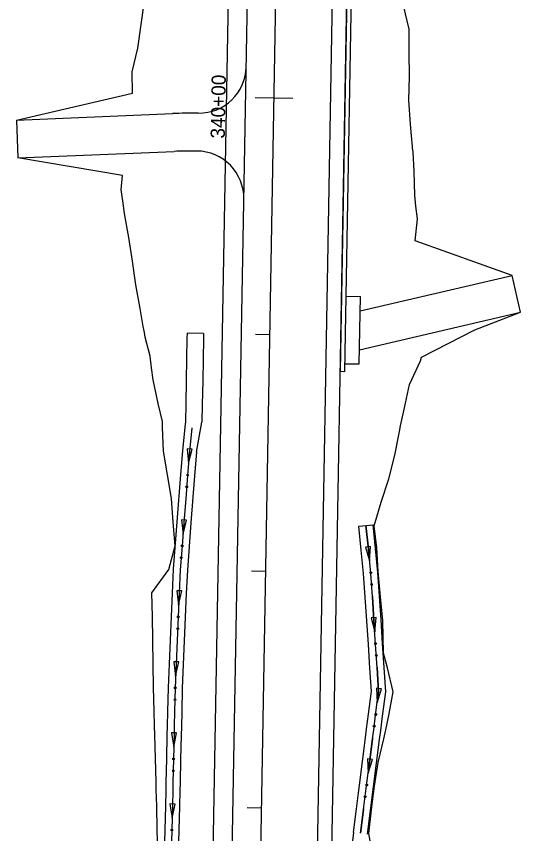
# Model space of a CAD drawing. Extents: x 948761 to 996004, y 1858548 to 1925175.
# Drawn here: x 960871.7 to 961084.7, y 1904759.1 to 1905104.5 of the extents above; entities that cross this region are included whole.
import ezdxf

# ---------------------------------------------------------------- set-up
doc = ezdxf.new("R2010")
doc.units = 0
for name, color, linetype in [('62', 7, 'Continuous'), ('R_Horz Alg', 7, 'Continuous'), ('R_Horz Alg Annot', 7, 'Continuous'), ('R_Proposed Const Limits', 7, 'Continuous'), ('R_Proposed Road', 7, 'Continuous')]:
    doc.layers.add(name, color=color, linetype=linetype)

msp = doc.modelspace()

# ---------------------------------------------------------------- linework, layer by layer
at = {"layer": '62'}
for p, q in [((960950.79, 1904970.5), (960943.79, 1904970.63)), ((960947.84, 1904920.32), (960950.12, 1904932.95)), ((960945.99, 1904921.55), (960943.88, 1904921.72)), ((960943.88, 1904921.72), (960944.44, 1904915.65)), ((960944.44, 1904915.65), (960945.99, 1904921.55)), ((960943.62, 1904891.61), (960941.51, 1904891.77)), ((960941.51, 1904891.77), (960942.1, 1904885.71)), ((960942.1, 1904885.71), (960943.62, 1904891.61)), ((961016.39, 1904888.98), (961022.36, 1904889.58)), ((961021.33, 1904880.43), (961019.22, 1904880.22)), ((961019.22, 1904880.22), (961020.87, 1904874.35)), ((961020.87, 1904874.35), (961021.33, 1904880.43)), ((960941.56, 1904861.68), (960939.45, 1904861.77)), ((960939.45, 1904861.77), (960940.26, 1904855.73)), ((960940.26, 1904855.73), (960941.56, 1904861.68)), ((961023.73, 1904850.45), (961021.62, 1904850.32)), ((961021.62, 1904850.32), (961023.06, 1904844.4)), ((961023.06, 1904844.4), (961023.73, 1904850.45)), ((960940.3, 1904831.67), (960938.19, 1904831.75)), ((960938.19, 1904831.75), (960939, 1904825.72)), ((960939, 1904825.72), (960940.3, 1904831.67)), ((961025.9, 1904820.27), (961023.8, 1904820.54)), ((961023.8, 1904820.54), (961024.09, 1904814.45)), ((961024.09, 1904814.45), (961025.9, 1904820.27)), ((960939.41, 1904801.66), (960937.3, 1904801.71)), ((960937.3, 1904801.71), (960938.22, 1904795.69)), ((960938.22, 1904795.69), (960939.41, 1904801.66)), ((961022.1, 1904790.47), (961020, 1904790.74)), ((961020, 1904790.74), (961020.29, 1904784.65)), ((961020.29, 1904784.65), (961022.1, 1904790.47)), ((960938.72, 1904771.63), (960936.6, 1904771.68)), ((960936.6, 1904771.68), (960937.51, 1904765.66)), ((960937.51, 1904765.66), (960938.72, 1904771.63))]:
    msp.add_line(p, q, dxfattribs=at)
for points in [[(960943.79, 1904970.63), (960943.75, 1904968.63), (960943.43, 1904950.63), (960943.26, 1904940.63), (960943.13, 1904933.2), (960942.89, 1904930.89), (960941.86, 1904920.88), (960941.04, 1904910.85), (960939.49, 1904890.87), (960937.94, 1904870.85), (960937.47, 1904860.8), (960936.21, 1904830.81), (960935.8, 1904820.79), (960935.57, 1904810.76), (960935.42, 1904804.59), (960935.33, 1904800.77), (960935.1, 1904790.77), (960934.86, 1904780.77), (960934.79, 1904777.53), (960934.64, 1904770.78), (960934.38, 1904760.78), (960934.12, 1904750.79)], [(960950.79, 1904970.5), (960950.79, 1904970.5), (960950.75, 1904968.5), (960950.43, 1904950.51), (960950.26, 1904940.51), (960950.12, 1904932.95)], [(960945.88, 1904930.58), (960944.85, 1904920.6), (960944.03, 1904910.61), (960943.26, 1904900.62), (960942.48, 1904890.64), (960941.71, 1904880.65), (960940.94, 1904870.66), (960940.46, 1904860.67), (960940.04, 1904850.67), (960939.62, 1904840.68), (960939.2, 1904830.69), (960938.8, 1904820.69), (960938.57, 1904810.69), (960938.42, 1904804.52), (960938.33, 1904800.7), (960938.1, 1904790.7), (960937.86, 1904780.7), (960937.79, 1904777.46), (960937.64, 1904770.7), (960937.38, 1904760.71), (960937.12, 1904750.71)], [(960945.88, 1904930.58), (960944.85, 1904920.6), (960944.44, 1904915.65)], [(960947.84, 1904920.32), (960947.02, 1904910.37), (960945.47, 1904890.41), (960943.93, 1904870.47), (960943.46, 1904860.53), (960942.62, 1904840.55), (960942.2, 1904830.56), (960941.8, 1904820.6), (960941.57, 1904810.62), (960941.42, 1904804.45), (960941.33, 1904800.63), (960941.1, 1904790.63), (960940.86, 1904780.63), (960940.79, 1904777.39), (960940.63, 1904770.63), (960940.38, 1904760.63), (960940.12, 1904750.63)], [(960943.26, 1904900.66), (960943.26, 1904900.62), (960942.48, 1904890.64), (960942.1, 1904885.71)], [(960943.26, 1904900.7), (960943.26, 1904900.66)], [(961014.09, 1904759.67), (961015.34, 1904769.66), (961016.21, 1904776.4), (961016.62, 1904779.64), (961017.9, 1904789.62), (961019.17, 1904799.6), (961019.66, 1904803.41), (961020.44, 1904809.57), (961021.68, 1904819.27), (961021.06, 1904828.99), (961020.41, 1904839), (961019.76, 1904849.02), (961019.1, 1904859.02), (961018.4, 1904868.98), (961017.4, 1904878.96), (961016.39, 1904888.98)], [(961017.07, 1904759.3), (961018.32, 1904769.28), (961019.18, 1904776.02), (961019.6, 1904779.26), (961020.87, 1904789.24), (961022.14, 1904799.22), (961022.63, 1904803.03), (961023.42, 1904809.2), (961024.69, 1904819.17), (961024.06, 1904829.19), (961023.4, 1904839.2), (961022.75, 1904849.21), (961022.1, 1904859.23), (961021.39, 1904869.24), (961020.38, 1904879.26), (961019.38, 1904889.28)], [(961019.38, 1904889.28), (961020.38, 1904879.26), (961020.87, 1904874.35)], [(961020.04, 1904758.93), (961021.29, 1904768.9), (961022.16, 1904775.64), (961022.57, 1904778.88), (961023.85, 1904788.86), (961025.12, 1904798.84), (961025.61, 1904802.65), (961026.39, 1904808.82), (961027.7, 1904819.08), (961027.05, 1904829.38), (961026.4, 1904839.4), (961025.74, 1904849.41), (961025.09, 1904859.43), (961024.38, 1904869.5), (961023.37, 1904879.56), (961022.36, 1904889.58)], [(960940.94, 1904870.71), (960940.94, 1904870.66), (960940.46, 1904860.67), (960940.26, 1904855.73)], [(960940.94, 1904870.75), (960940.94, 1904870.71)], [(961022.08, 1904859.4), (961022.09, 1904859.37)], [(961022.09, 1904859.37), (961022.1, 1904859.23), (961022.75, 1904849.21), (961023.06, 1904844.4)], [(960939.62, 1904840.7), (960939.62, 1904840.68), (960939.2, 1904830.69), (960939, 1904825.72)], [(960939.63, 1904840.74), (960939.62, 1904840.7)], [(961024.04, 1904829.43), (961024.04, 1904829.39)], [(961024.04, 1904829.39), (961024.06, 1904829.19), (961024.69, 1904819.17), (961024.09, 1904814.45)], [(960938.57, 1904810.69), (960938.42, 1904804.52), (960938.33, 1904800.7), (960938.22, 1904795.69)], [(960938.57, 1904810.72), (960938.57, 1904810.69), (960938.57, 1904810.69)], [(961022.18, 1904799.53), (961022.14, 1904799.22), (961020.87, 1904789.24), (961020.29, 1904784.65)], [(961022.19, 1904799.57), (961022.18, 1904799.53)], [(960937.86, 1904780.66), (960937.79, 1904777.46), (960937.64, 1904770.7), (960937.51, 1904765.66)], [(960937.86, 1904780.69), (960937.86, 1904780.66)], [(961018.38, 1904769.74), (961018.32, 1904769.28), (961017.07, 1904759.3)], [(961018.38, 1904769.78), (961018.38, 1904769.74)], [(961014.09, 1904759.67), (961012.89, 1904749.27), (961012.54, 1904729.37), (961012.36, 1904719.38), (961012.18, 1904709.38), (961012.01, 1904699.38), (961011.93, 1904695.15), (961011.93, 1904694.76), (961011.82, 1904689.33), (961011.66, 1904681.02)]]:
    msp.add_lwpolyline(points, dxfattribs=at)
for centre in [(960944.07, 1904910.66), (960943.68, 1904905.67), (960941.75, 1904880.71), (960941.36, 1904875.72), (961021.41, 1904869.38), (961021.77, 1904864.38), (960940.08, 1904850.73), (960939.87, 1904845.72), (961023.43, 1904839.41), (961023.75, 1904834.41), (960938.84, 1904820.71), (960938.72, 1904815.7), (961023.49, 1904809.48), (961022.86, 1904804.51), (960938.13, 1904790.68), (960938.02, 1904785.68), (961019.69, 1904779.68), (961019.05, 1904774.72), (960937.41, 1904760.65)]:
    msp.add_circle(centre, 0.375, dxfattribs=at)
at = {"layer": 'R_Horz Alg'}
msp.add_line((960973.94, 1904695.88), (960986.27, 1905393.73), dxfattribs=at)
at = {"layer": 'R_Horz Alg Annot'}
for points in [[(960972.55, 1905070.13), (960988.55, 1905069.85)], [(960972.78, 1904970.11), (960978.78, 1904970.01)], [(960971.02, 1904870.13), (960977.02, 1904870.02)], [(960969.25, 1904770.15), (960975.25, 1904770.04)]]:
    msp.add_lwpolyline(points, dxfattribs=at)
at = {"layer": 'R_Proposed Const Limits'}
for points in [[(960871.71, 1905060.63), (960920.71, 1905072), (960920.6, 1905081.05), (960923.03, 1905091.01), (960924.37, 1905100.99), (960925.82, 1905110.97), (960927.57, 1905120.94), (960928.21, 1905124.71), (960928.68, 1905124.71), (960928.83, 1905124.71), (960930.45, 1905130.89), (960935.7, 1905140.8), (960940.79, 1905150.71), (960944.49, 1905160.64), (960945.18, 1905167.8), (960945.05, 1905168.82), (960926.09, 1905178.97)], [(961081.08, 1904995), (961040.13, 1905009.64), (961041.09, 1905018.92), (961040.43, 1905024.27), (961039.95, 1905028.94), (961039.74, 1905038.94), (961039.32, 1905047.07), (961039.09, 1905048.96), (961039.03, 1905049.53), (961038.59, 1905053.97), (961038.16, 1905058.97), (961037.52, 1905068.99), (961037.81, 1905078.98), (961037.68, 1905088.99), (961037.56, 1905098.99), (961035.2, 1905109.03)], [(960933.37, 1904930.8), (960933.42, 1904933.25), (960931.56, 1904940.84), (960929.44, 1904950.88), (960928.84, 1904955.89), (960928.2, 1904960.9), (960926.18, 1904968.94), (960925.8, 1904970.94), (960925.33, 1904973.38), (960923.97, 1904980.98), (960922.21, 1904991.01), (960920.71, 1905001.04), (960919.22, 1905011.07), (960917.44, 1905021.1), (960916.72, 1905026.45), (960916, 1905031.13), (960916.56, 1905037.27), (960872.38, 1905044.65)], [(961022.82, 1904889.22), (961025.8, 1904899.17), (961029.09, 1904909.11), (961031.57, 1904919.07), (961033.47, 1904929.04), (961034.01, 1904931.47), (961035.68, 1904939), (961037.79, 1904948.96), (961042.35, 1904958.88), (961042.84, 1904960.42), (961065.34, 1904972.04), (961084.71, 1904979.41)], [(960931.5, 1904750.81), (960931.25, 1904760.81), (960931, 1904770.82), (960930.82, 1904777.58), (960930.73, 1904780.83), (960930.47, 1904790.83), (960930.21, 1904800.84), (960930.11, 1904804.67), (960929.95, 1904810.85), (960929.69, 1904820.85), (960929.51, 1904830.86), (960929.34, 1904840.86), (960929.17, 1904850.87), (960929, 1904860.87), (960936.13, 1904870.75), (960938.84, 1904880.7), (960938.01, 1904890.72), (960937.19, 1904900.73), (960935.5, 1904910.76), (960933.88, 1904920.79), (960933.37, 1904930.8)], [(961022.41, 1904749.2), (961020.61, 1904759.24), (961021.69, 1904769.22), (961022.59, 1904775.96), (961023.01, 1904779.2), (961024.48, 1904789.17), (961026.9, 1904799.13), (961027.83, 1904802.94), (961029.02, 1904809.1), (961030.9, 1904819.06), (961028.41, 1904829.11), (961026.84, 1904835.36), (961026.45, 1904849.15), (961025.57, 1904859.16), (961024.57, 1904869.93), (961023.96, 1904879.95), (961022.82, 1904889.22)]]:
    msp.add_lwpolyline(points, dxfattribs=at)
at = {"layer": 'R_Proposed Road'}
for p, q in [((960953.94, 1904696.23), (960966.27, 1905394.08)), ((960961.94, 1904696.09), (960974.27, 1905393.94)), ((960997.94, 1904695.46), (961010.26, 1905393.31)), ((961003.93, 1904695.35), (961016.26, 1905393.2)), ((960871.71, 1905060.63), (960937.68, 1905063.38)), ((960871.71, 1905060.63), (960872.38, 1905044.65)), ((960872.38, 1905044.65), (960938.35, 1905047.4)), ((961016.97, 1904980.07), (961081.08, 1904995)), ((961084.71, 1904979.41), (961081.08, 1904995)), ((961011.07, 1904986.18), (961017.07, 1904986.07)), ((961016.67, 1904963.57), (961084.71, 1904979.41)), ((961010.57, 1904957.68), (961016.57, 1904957.58))]:
    msp.add_line(p, q, dxfattribs=at)
msp.add_lwpolyline([(961008.51, 1904954.48), (961010.51, 1904954.45), (961014.31, 1905169.41), (961012.31, 1905169.45)], close=True, dxfattribs=at)
msp.add_lwpolyline([(961016.57, 1904957.58), (961017.07, 1904986.07)], dxfattribs=at)
for centre, radius, start, end in [((960948.78, 1905083.55), 20, 269.387, 358.988), ((960946.34, 1904855.56), 208, 89.387, 92.3862), ((960946.34, 1904855.56), 192, 89.5169, 92.3862), ((960947.79, 1905027.56), 20, 358.988, 89.5169)]:
    msp.add_arc(centre, radius, start, end, dxfattribs=at)

# ---------------------------------------------------------------- texts
at = {"layer": 'R_Horz Alg Annot'}
msp.add_text('340+00', height=6, rotation=88.988, dxfattribs=at).set_placement((960959.74, 1905052.78))

doc.saveas('drawing.dxf')
